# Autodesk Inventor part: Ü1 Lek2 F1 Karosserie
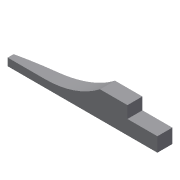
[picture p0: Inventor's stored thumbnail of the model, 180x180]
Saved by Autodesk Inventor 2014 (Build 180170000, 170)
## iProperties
Created: 2013-07
Part Number: Ü1 Lek2 F1 Karosserie
Material: Generisch
Document SubType Name: Modeling
Designer: Sofia
Density: 1 g/cm^3
Appearance: Vorgabe
Author: Sofia
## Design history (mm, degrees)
sketch "Skizze1"
  geometry: L1 (0, 0)-(200, 0); L2 (200, 0)-(200, 20); L3 (200, 20)-(110, 20); L4 (0, 8)-(0, 0); A1 r 510.167 centre (110, -490.167) between (110, 20) and (0, 8)
  constraints: 8 end point, 2 perpendicular, 2 point on circle, 1 centre point, 1 horizontal, 1 parallel, 1 tangent
  dimensions: "d2" = 200 distance of L1.start L1.end; "d3" = 20 distance of L1.end L2.end; "d4" = 90 distance of L2.end L3.end; "d5" = 8 distance of L4.start L1.start
extrude "Extrusion1" new body sketch "Skizze1" distance "d6" = 35; taper "d7" = 0 deg
sketch "Skizze2"
  geometry: L1 (0, 0)-(200, 0) reference; L2 (0, 35)-(200, 35) reference; L3 (0, 0)-(0, 35) reference; L4 (0, 10)-(50, 10); L5 (200, 35)-(160, 35); L6 (160, 35)-(160, 19); L7 (160, 19)-(200, 19); L8 (200, 19)-(200, 35); A1 r 120 centre (50, 130) between (50, 10) and (123.314, 35)
  constraints: 10 end point, 2 parallel, 2 perpendicular, 2 point on circle, 2 point on line, 1 centre point, 1 horizontal, 1 tangent
  dimensions: "d8" = 50 distance of L4.start L4.end; "d9" = 10 distance between parallel lines of L4 L1; "d10" = 120 radius of A1; "d13" = 40 distance of L7.end L6.end; "d14" = 16 distance of L6.end L5.end
extrude "Extrusion2" cut sketch "Skizze2" stored distance "d15" = 35; taper "d16" = 0 deg
node "Volumenkörper1"
